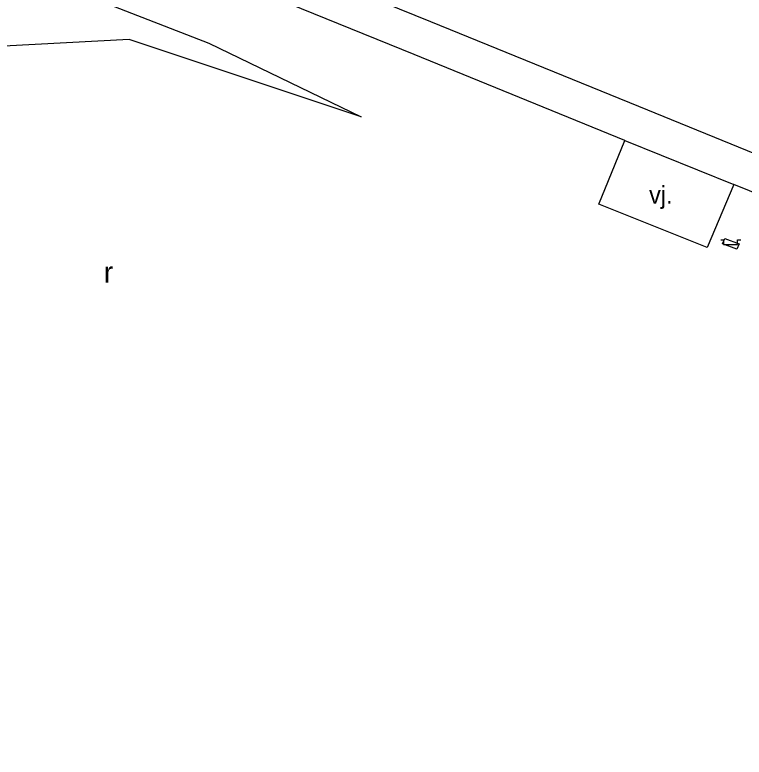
# Model space of a CAD drawing. Extents: x -836568 to -836015, y -1070547 to -1070212.
# Drawn here: x -836360.58 to -836329.46, y -1070447.97 to -1070416.28 of the extents above; entities that cross this region are included whole.
import ezdxf

# ---------------------------------------------------------------- set-up
doc = ezdxf.new("R2010")
doc.units = 0
for name, color, linetype in [('BodPole_mer', 7, 'Continuous'), ('Doprava_hranice', 7, 'Continuous'), ('Doprava_kody', 7, 'Continuous'), ('OstPloch_hranice', 7, 'Continuous'), ('OstPloch_kody', 7, 'Continuous'), ('PovrZnIS_hranice', 7, 'Continuous'), ('PovrZnIS_kody', 7, 'Continuous')]:
    doc.layers.add(name, color=color, linetype=linetype)

msp = doc.modelspace()

# ---------------------------------------------------------------- linework, layer by layer
at = {"layer": 'BodPole_mer'}
for p, q in [((-836342.84, -1070416.58), (-836342.84, -1070416.58)), ((-836355.7, -1070417.34), (-836355.7, -1070417.34)), ((-836352.3, -1070417.49), (-836352.3, -1070417.49)), ((-836343.54, -1070417.97), (-836343.54, -1070417.97)), ((-836333.96, -1070420.19), (-836333.96, -1070420.19)), ((-836345.8, -1070420.64), (-836345.8, -1070420.64)), ((-836334.55, -1070421.64), (-836334.55, -1070421.64)), ((-836329.9, -1070423.52), (-836329.9, -1070423.52)), ((-836335.67, -1070424.36), (-836335.67, -1070424.36)), ((-836330.29, -1070425.83), (-836330.29, -1070425.83)), ((-836330.29, -1070425.83), (-836330.29, -1070425.83)), ((-836330.38, -1070426.06), (-836330.38, -1070426.06)), ((-836330.38, -1070426.06), (-836330.38, -1070426.06)), ((-836329.68, -1070426.06), (-836329.68, -1070426.06)), ((-836329.68, -1070426.06), (-836329.68, -1070426.06)), ((-836331.04, -1070426.22), (-836331.04, -1070426.22)), ((-836329.77, -1070426.29), (-836329.77, -1070426.29)), ((-836329.77, -1070426.29), (-836329.77, -1070426.29))]:
    msp.add_line(p, q, dxfattribs=at)
at = {"layer": 'Doprava_hranice'}
msp.add_line((-836334.55, -1070421.64), (-836329.9, -1070423.52), dxfattribs=at)
for points in [[(-836294.78, -1070436.14), (-836298.75, -1070434.54), (-836300.99, -1070433.61), (-836301.95, -1070433.21), (-836302.68, -1070432.9), (-836308.94, -1070430.38), (-836313.57, -1070428.51), (-836318.21, -1070426.63), (-836324.7, -1070423.98), (-836329.32, -1070422.08), (-836333.96, -1070420.19), (-836342.84, -1070416.58), (-836353.67, -1070412.18), (-836369.06, -1070405.92), (-836381.28, -1070400.95), (-836385.01, -1070399.41), (-836387.75, -1070398.25), (-836390.49, -1070397.04), (-836393.21, -1070395.81), (-836395.03, -1070394.97), (-836397.75, -1070393.68), (-836399.24, -1070392.97)], [(-836370.7, -1070410.27), (-836360.12, -1070414.44), (-836352.3, -1070417.49), (-836345.8, -1070420.64)], [(-836282.83, -1070440.54), (-836283.39, -1070441.99), (-836288.97, -1070439.98), (-836292.82, -1070438.51), (-836295.89, -1070437.33), (-836299.06, -1070436.06), (-836309.56, -1070431.79), (-836314.22, -1070429.91), (-836319.37, -1070427.82), (-836325.29, -1070425.39), (-836329.9, -1070423.52), (-836331.04, -1070426.22), (-836335.67, -1070424.36), (-836334.55, -1070421.64), (-836343.54, -1070417.97), (-836354.29, -1070413.6)]]:
    msp.add_lwpolyline(points, dxfattribs=at)
at = {"layer": 'OstPloch_hranice'}
msp.add_lwpolyline([(-836345.8, -1070420.64), (-836355.7, -1070417.34), (-836361.05, -1070417.62), (-836366.07, -1070418.7), (-836371.68, -1070421.97), (-836374.95, -1070424.71), (-836382.62, -1070447.97)], dxfattribs=at)
at = {"layer": 'PovrZnIS_hranice'}
msp.add_line((-836330.29, -1070425.83), (-836329.68, -1070426.06), dxfattribs=at)
msp.add_line((-836330.29, -1070425.83), (-836329.68, -1070426.06), dxfattribs=at)
msp.add_lwpolyline([(-836329.68, -1070426.06), (-836329.77, -1070426.29), (-836330.38, -1070426.06), (-836330.29, -1070425.83)], dxfattribs=at)
msp.add_lwpolyline([(-836329.68, -1070426.06), (-836329.77, -1070426.29), (-836330.38, -1070426.06), (-836330.29, -1070425.83)], dxfattribs=at)
at = {"layer": 'PovrZnIS_kody'}
for p, q in [((-836330.461, -1070425.88), (-836330.34, -1070425.88)), ((-836330.461, -1070425.88), (-836330.34, -1070425.88)), ((-836330.34, -1070425.88), (-836330.34, -1070426.08)), ((-836330.34, -1070425.88), (-836330.34, -1070426.08)), ((-836330.34, -1070426.08), (-836329.74, -1070426.08)), ((-836330.34, -1070426.08), (-836329.74, -1070426.08)), ((-836329.74, -1070426.08), (-836329.74, -1070425.88)), ((-836329.74, -1070425.88), (-836329.606, -1070425.88)), ((-836329.74, -1070426.08), (-836329.74, -1070425.88)), ((-836329.74, -1070425.88), (-836329.606, -1070425.88))]:
    msp.add_line(p, q, dxfattribs=at)

# ---------------------------------------------------------------- texts
at = {"layer": 'Doprava_kody'}
msp.add_text('vj.', height=0.75, dxfattribs=at).set_placement((-836333.52, -1070424.34))
at = {"layer": 'OstPloch_kody'}
msp.add_text('r', height=0.9, dxfattribs=at).set_placement((-836356.79, -1070427.72))

doc.saveas('drawing.dxf')
